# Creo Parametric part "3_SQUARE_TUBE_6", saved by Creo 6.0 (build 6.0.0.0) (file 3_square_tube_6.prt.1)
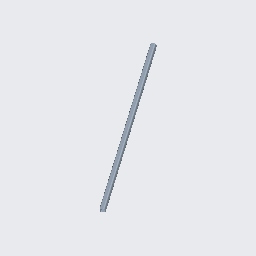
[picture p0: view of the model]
Units: Custom; MM, KILOGRAM, SECS
Materials in the file: STEEL

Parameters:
  BUW_NAME = "SQUARE TUBE"
  BUW_TYPE = "DIN EN 10219"
  BUW_SIZE = "25x25x3.0"
  BUW_LENGTH_STR = "910"
  PTC_MATERIAL_NAME = "STEEL"
  BUW_PROFIL_TYPE = "square_tube"
  BUW_PROFILE_PATH = "parts//profiles/steel_beams_mm/"
  BUW_PROFILE_NAME_LANG = "SQUARE TUBE"
  BUW_TAB_SEL_INFO = "-2 TYPE DIN_EN_10219-1997 SIZE_DINEN_10219 25x25x3.0"
  NAMING = "SQUARE TUBE"
  DESIGNATION = "DIN EN 10219 25x25x3.0 x 910"
  PROFIL_RASTER_POS = "X_0"
  BUW_OBJECT_ROLE = "PROFIL_SYSTEM_BORE_END_POINTS"
  PRO_UNIT_SYS = "Custom"

Other parameters: BUW_LENGTH, LENGTH, BUW_LENGTH_Z_MIN_PARAM, D8, D93, D94, d26, d8, d93, d94, d98, D98, SHEAR_MODULUS, THERM_EXPANSION_REF_TEMPERATURE, STRUCTURAL_DAMPING_COEFFICIENT, STRESS_LIMIT_FOR_TENSION, STRESS_LIMIT_FOR_COMPRESSION, STRESS_LIMIT_FOR_SHEAR, EMISSIVITY

Created from: SQUARE_TUBE.PRT

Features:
  1. datum plane "YZ"
  2. datum plane "XZ"
  3. datum plane "XY"
  4. coordinate system
  5. coordinate system
  6. coordinate system
  7. coordinate system
  8. datum plane "DTM3"
  9. datum plane "DTM4"
  10. datum plane "DTM5"
  11. protrusion
  12. round
  13. round
  14. datum axis
  15. datum point "PNT0"
  16. datum point

Other named items: PROFIL_CUT_QUILT, PROFILE_LENGTH_DIM, CONTACT_SURF_3, CONTACT_SURF_2, CONTACT_SURF_1, CONTACT_SURF_0, E, START_SURFACE, END_SURFACE, SIDE_SURF_3, SIDE_SURF_0, SIDE_SURF_1, SIDE_SURF_2, EDGE_7_S, EDGE_7_E, EDGE_1_S, EDGE_1_E, EDGE_3_S, EDGE_3_E, EDGE_5_S, EDGE_5_E, EDGE_6_S, EDGE_4_S, EDGE_2_S, EDGE_0_S, EDGE_6_E, EDGE_4_E, EDGE_2_E, EDGE_0_E, CS0, CS_S, CS_E, CS3

Named dimensions: X_ROT_S, Y_ROT_S, Z_OFF_S, X_ROT_E, Y_ROT_E, Z_OFF_E, PC_L, BUW_LENGTH_Z_MIN, BUW_LENGTH_DIM

Layers: 00_PROFIL_DATUM, 00_PROFIL_DRW_HIDE, 00_PROFIL_END_CSYS, 00_PROFIL_GEOMETRY, 00_PROFIL_QUILT, 00_PROFIL_SIZE_NOTE

Surfaces: 16 plane, 12 cylinder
